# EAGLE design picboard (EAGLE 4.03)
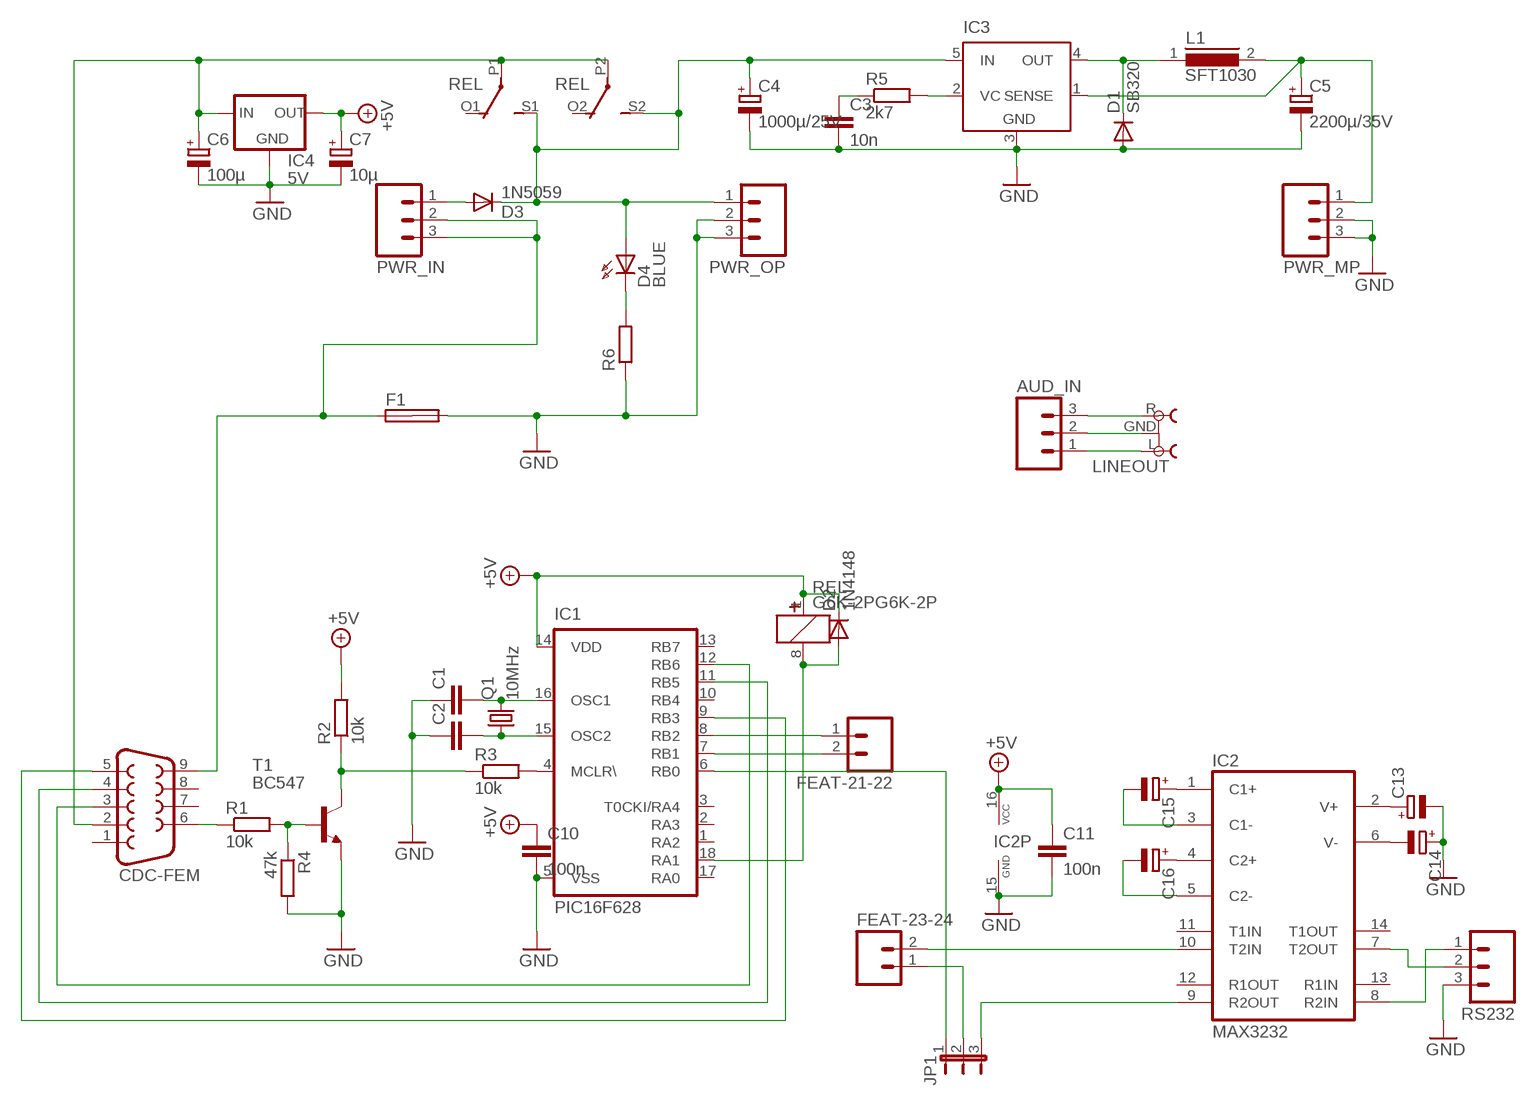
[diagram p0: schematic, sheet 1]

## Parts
AUD_IN  M03  [03P]
C1  C-EU025-024X044  [C025-024X044]
C2  C-EU025-024X044  [C025-024X044]
C3  10n  C-EU025-024X044  [C025-024X044]
C4  1000µ/25V  CPOL-EUE5-13  [E5-13]
C5  2200µ/35V  CPOL-EUE7.5-16  [E7,5-16]
C6  100µ  CPOL-EUE2.5-6  [E2,5-6]
C7  10µ  CPOL-EUE2.5-5  [E2,5-5]
C10  100n  C-EU025-024X044  [C025-024X044]
C11  100n  C-EU025-024X044  [C025-024X044]
C13  CPOL-EUE2.5-5  [E2,5-5]
C14  CPOL-EUE2.5-5  [E2,5-5]
C15  CPOL-EUE2.5-5  [E2,5-5]
C16  CPOL-EUE2.5-5  [E2,5-5]
CDC-FEM  F09H  [F09H]
D1  SB320  [DO201-15]
D2  1N4148  [DO35-10]
D3  1N5059  [DO204-10]
D4  BLUE  LED3MM  [LED3MM]
F1  SHK20L  [SHK20L]
FEAT-21-22  M02  [02P]
FEAT-23-24  M02  [02P]
IC1  PIC16F628  PIC16F84AP  [DIL18]
IC2  MAX3232  [DIL16]
IC3  MAX787  [TO220-5]
IC4  5V  78LXX  [78LXX]
JP1  JP2E  [JP2]
L1  SFT1030  [SFT1030]
LINEOUT  CINCH_REICHELTCINCH_2X  [CINCH_2X]
PWR_IN  M03  [03P]
PWR_MP  M03  [03P]
PWR_OP  M03  [03P]
Q1  10MHz  HC49U70  [HC49U70]
R1  10k  R-EU_0207/10  [0207/10]
R2  10k  R-EU_0207/2V  [0207/2V]
R3  10k  R-EU_0207/10  [0207/10]
R4  47k  R-EU_0207/2V  [0207/2V]
R5  2k7  R-EU_0207/10  [0207/10]
R6  R-EU_0207/10  [0207/10]
REL  G6K-2PG6K-2P  [G6K-2P]
RS232  M03  [03P]
T1  BC547  [TO92]

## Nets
+5V: C7.+ C10.2 C11.2 D2.C IC1.14(VDD) IC2.16(VCC) IC4.OUT R2.2 REL.1
+5V-SW: C5.+ IC3.1(SENSE) L1.2 PWR_MP.1
GND: C1.2 C2.2 C3.1 C4.- C5.- C6.- C7.- C10.1 C11.1 C13.- C14.+ D1.A F1.2A IC1.5(VSS) IC2.15(GND) IC3.3(GND) IC4.GND PWR_MP.2 PWR_MP.3 PWR_OP.2 PWR_OP.3 R4.2 R6.1 RS232.3 T1.1(E)
N$1: C6.+ CDC-FEM.2 IC4.IN REL.P1(P) REL.P2(P)
N$2: CDC-FEM.3 IC1.12(RB6)
N$3: CDC-FEM.4 IC1.11(RB5)
N$4: CDC-FEM.5 IC1.9(RB3)
N$5: C1.1 IC1.16(OSC1) Q1.2
N$6: CDC-FEM.6 R1.1
N$7: R1.2 R4.1 T1.2(B)
N$8: R2.1 R3.1 T1.3(C)
N$9: C4.+ D3.C D4.A IC3.5(IN) PWR_OP.1 REL.S1(S) REL.S2(S)
N$10: IC1.4(MCLR\) R3.2
N$11: C2.1 IC1.15(OSC2) Q1.1
N$12: CDC-FEM.9 F1.1A PWR_IN.2 PWR_IN.3
N$13: D1.C IC3.4(OUT) L1.1
N$14: D3.A PWR_IN.1
N$15: D2.A IC1.18(RA1) REL.8
N$16: FEAT-21-22.1 IC1.8(RB2)
N$17: IC1.6(RB0) JP1.1
N$18: IC2.9(R2OUT) JP1.3
N$19: FEAT-23-24.1 JP1.2
N$20: FEAT-23-24.2 IC2.10(T2IN)
N$21: FEAT-21-22.2 IC1.7(RB1)
N$23: IC2.8(R2IN) RS232.1
N$24: IC3.2(VC) R5.2
N$25: IC2.7(T2OUT) RS232.2
N$27: C3.2 R5.1
N$28: AUD_IN.3 LINEOUT.R
N$29: D4.K(C) R6.2
N$34: C15.+ IC2.1(C1+)
N$35: C15.- IC2.3(C1-)
N$36: C16.+ IC2.4(C2+)
N$37: C16.- IC2.5(C2-)
N$41: AUD_IN.1 LINEOUT.L
N$42: C14.- IC2.6(V-)
N$43: C13.+ IC2.2(V+)
N$44: AUD_IN.2 LINEOUT.GND
Unconnected: CDC-FEM.1 CDC-FEM.7 CDC-FEM.8 F1.1B F1.2B IC1.1(RA2) IC1.2(RA3) IC1.3(T0CKI/RA4) IC1.10(RB4) IC1.13(RB7) IC1.17(RA0) IC2.11(T1IN) IC2.12(R1OUT) IC2.13(R1IN) IC2.14(T1OUT) REL.O1(O) REL.O2(O)

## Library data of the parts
AUD_IN PWR_IN PWR_MP PWR_OP RS232 = con-amp-quick:M03: AMP QUICK CONNECTOR
C1-C3 C10 C11 = rcl:C-EU: CAPACITOR, European symbol
C4-C7 C13-C16 = rcl:CPOL-EU: POLARIZED CAPACITOR, European symbol
CDC-FEM = con-subd:F09H: HARTING SUB-D
D1 = diode:SB320: DIODE
D2 = diode:1N4148: DIODE
D3 = diode:1N5059: DIODE
D4 = led:LED3MM: LED
F1 = fuse:SHK20L: FUSE HOLDER 5 x 20 mm, SH contact, SHH1 Schukat, E1073 Buerklin
FEAT-21-22 FEAT-23-24 = con-amp-quick:M02: AMP QUICK CONNECTOR
IC1 = microchip:PIC16F8*: MICROCONTROLLER 8-Bit PIC16F8X Family - CMOS Flash/EEPROM Pin Compatible : PIC16F83, PIC16CR83, PIC16F84A, PIC16CR84 see also PIC16C*
IC2 = maxim:MAX3232: RS232 TRANSEIVER
IC3 = _mylib:MAX787: VOLTAGE REGULATOR with shutdown
IC4 = v-reg:78LXX: VOLTAGE REGULATOR
JP1 = jumper:JP2E: JUMPER
L1 = inductors:SFT1030: INDUCTOR
LINEOUT = _mylib:CINCH_REICHELT
Q1 = crystal:HC49U70: CRYSTAL
R1-R6 = rcl:R-EU_: RESISTOR, European symbol
REL = _mylib:G6K-2P
T1 = transistor-npn:BC547: NPN TRANSISTOR

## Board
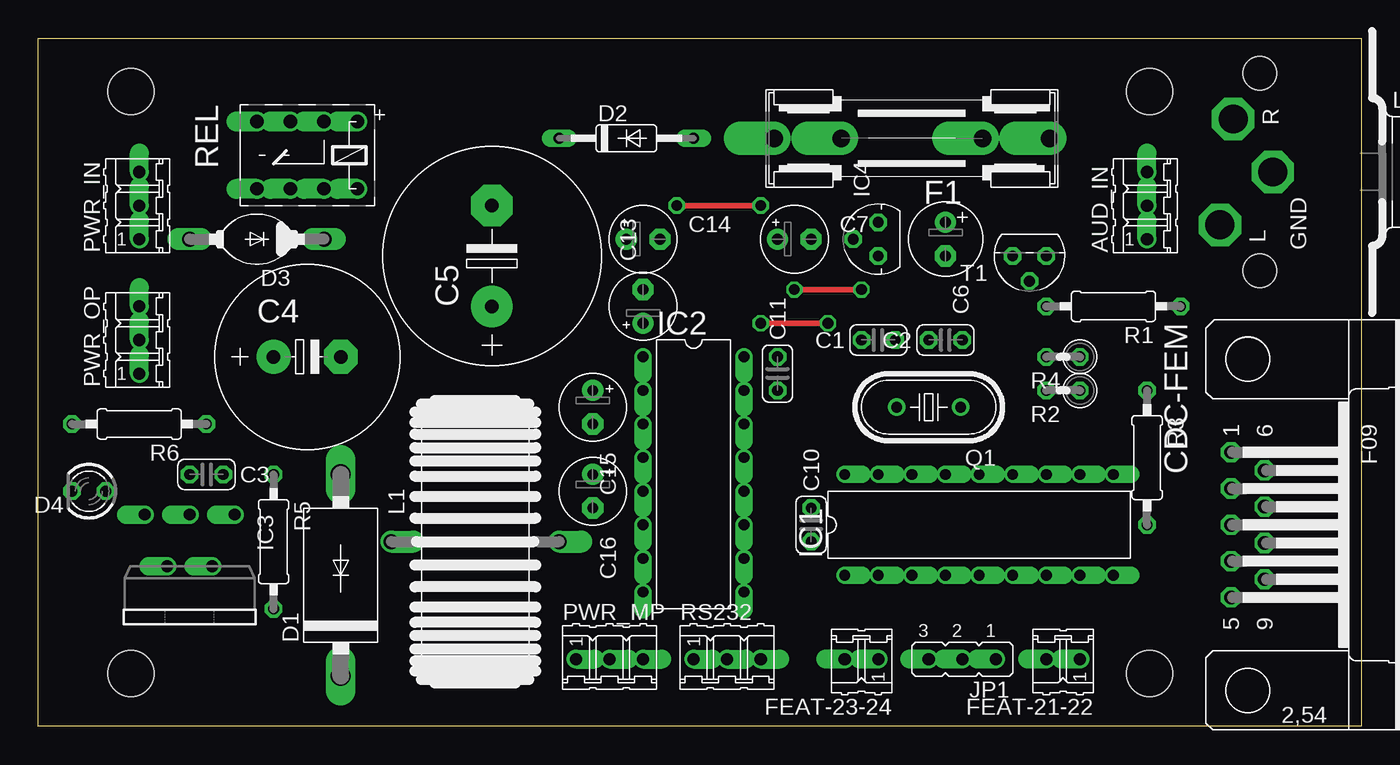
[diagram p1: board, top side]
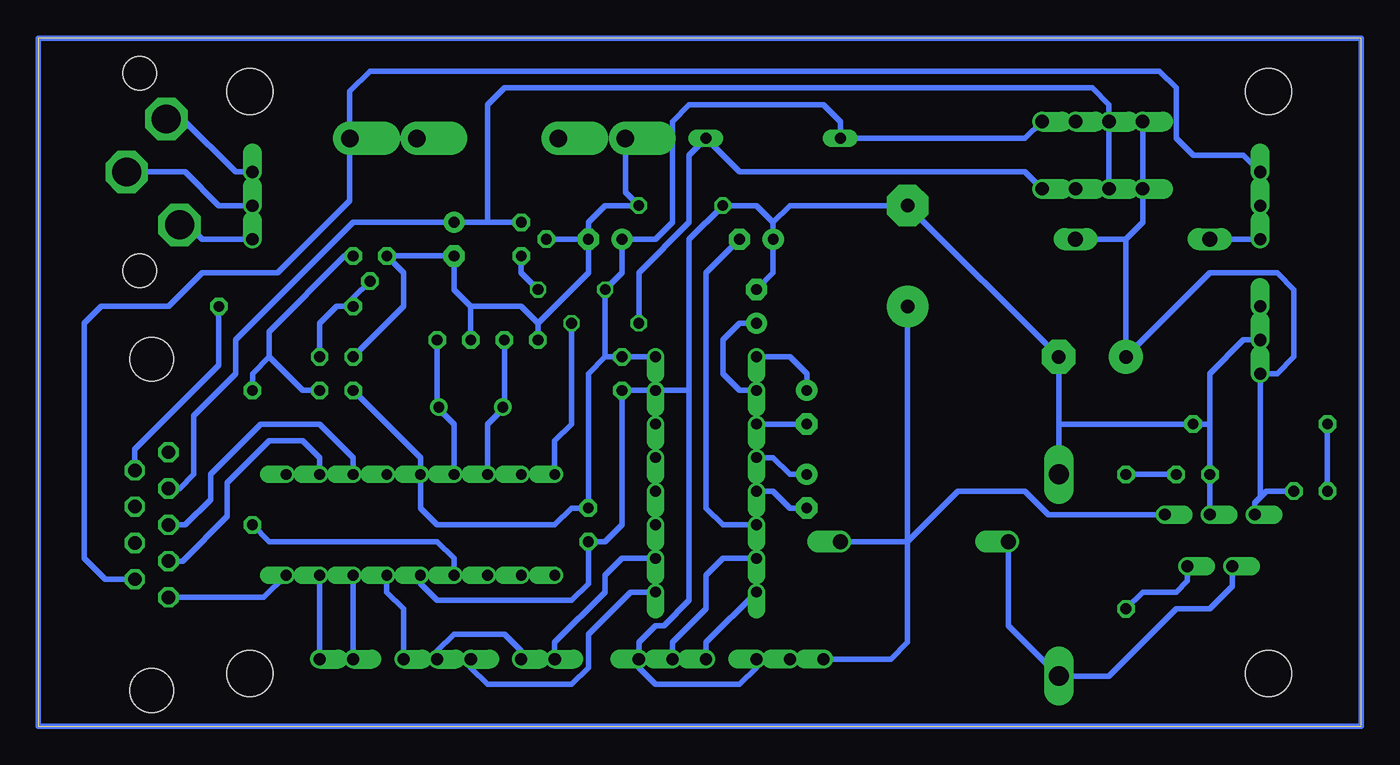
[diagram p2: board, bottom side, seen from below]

Size 100 x 52 mm. Coordinates in mm from the lower left corner, seen from the top.
Outline: 0,0 0,52 100,52 100,0 0,0
Copper layers used: Top, Bottom
Holes 3.5 mm at 7,48 7,4 84,4 84,48

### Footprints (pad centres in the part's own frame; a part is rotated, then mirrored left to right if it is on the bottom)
03P = drill 0.914 offset: 1 -2.54,0; 2 0,0; 3 2.54,0
C025-024X044 = drill 0.813 octagon: 1 -1.27,0; 2 1.27,0
E5-13 = drill 1.016 pad 2.54 round: + -2.54,0 | drill 1.016 pad 2.54 octagon: - 2.54,0
E7,5-16 = drill 1.016 pad 3.15 round: + -3.81,0 | drill 1.016 pad 3.15 octagon: - 3.81,0
E2,5-6 = drill 0.813 pad 1.6 round: + -1.27,0 | drill 0.813 pad 1.6 octagon: - 1.27,0
E2,5-5 = drill 0.813 pad 1.6 round: + -1.27,0 | drill 0.813 pad 1.6 octagon: - 1.27,0
F09H = drill 1.016 octagon: 1 -5.486,-1.27; 2 -2.743,-1.27; 3 0,-1.27; 4 2.743,-1.27; 5 5.486,-1.27; 6 -4.115,1.27; 7 -1.372,1.27; 8 1.372,1.27; 9 4.115,1.27 | hole 3.302: -12.522,0; 12.522,0
DO201-15 = drill 1.499 long: A 7.62,0; C -7.62,0
DO35-10 = drill 0.813 long: A 5.08,0; C -5.08,0
DO204-10 = drill 1.118 long: A 5.08,0; C -5.08,0
LED3MM = drill 0.813 octagon: A -1.27,0; K 1.27,0
SHK20L = drill 1.321 pad 2.54 offset: 1A -10.414,0; 1B -5.334,0; 2A 10.414,0; 2B 5.334,0
02P = drill 0.914 offset: 1 -1.27,0; 2 1.27,0
DIL18 = drill 0.813 offset: 1 -10.16,-3.81; 2 -7.62,-3.81; 3 -5.08,-3.81; 4 -2.54,-3.81; 5 0,-3.81; 6 2.54,-3.81; 7 5.08,-3.81; 8 7.62,-3.81; 9 10.16,-3.81; 10 10.16,3.81; 11 7.62,3.81; 12 5.08,3.81; 13 2.54,3.81; 14 0,3.81; 15 -2.54,3.81; 16 -5.08,3.81; 17 -7.62,3.81; 18 -10.16,3.81
DIL16 = drill 0.813 offset: 1 -8.89,-3.81; 2 -6.35,-3.81; 3 -3.81,-3.81; 4 -1.27,-3.81; 5 1.27,-3.81; 6 3.81,-3.81; 7 6.35,-3.81; 8 8.89,-3.81; 9 8.89,3.81; 10 6.35,3.81; 11 3.81,3.81; 12 1.27,3.81; 13 -1.27,3.81; 14 -3.81,3.81; 15 -6.35,3.81; 16 -8.89,3.81
TO220-5 = drill 0.9 offset: 1 -3.4,-8.4; 2 -1.7,-4.5; 3 0,-8.4; 4 1.7,-4.5; 5 3.4,-8.4
78LXX = drill 0.813 octagon: GND 0,1.905; IN 1.27,0; OUT -1.27,0
JP2 = drill 0.914 offset: 1 -2.54,0; 2 0,0; 3 2.54,0
SFT1030 = drill 1.118 offset: 1 -6.35,0; 2 6.35,0
CINCH_2X = drill 2.184 octagon: GND 0,-7; L 4,-11; R -4,-10 | hole 2.54: -7.46,-8; 7.46,-8
HC49U70 = drill 0.813 round: 1 -2.413,0; 2 2.413,0
0207/10 = drill 0.813 octagon: 1 -5.08,0; 2 5.08,0
0207/2V = drill 0.813 octagon: 1 -1.27,0; 2 1.27,0
G6K-2P = drill 1.016 offset: 1 -3.81,-3.81; 8 -3.81,1.27; O1 -1.27,-3.81; O2 -1.27,1.27; P1 1.27,-3.81; P2 1.27,1.27; S1 3.81,-3.81; S2 3.81,1.27
TO92 = drill 0.813 octagon: 1 1.27,0; 2 0,1.905; 3 -1.27,0

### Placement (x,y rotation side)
AUD_IN  83.82,39.37 90 top
C1  63.5,29.21 180 top
C2  68.58,29.21 180 top
C3  12.7,19.05 0 top
C4  20.32,27.94 0 top
C5  34.29,35.56 90 top
C6  68.58,36.83 270 top
C7  57.15,36.83 0 top
C10  58.42,15.24 90 top
C11  55.88,26.67 90 top
C13  45.72,31.75 90 top
C14  45.72,36.83 0 top
C15  41.91,24.13 270 top
C16  41.91,17.78 270 top
CDC-FEM  91.44,15.24 270 top
D1  22.86,11.43 90 top
D2  44.45,44.45 0 top
D3  16.51,36.83 180 top
D4  3.81,17.78 180 top
F1  66.04,44.45 180 top
FEAT-21-22  77.47,5.08 180 top
FEAT-23-24  62.23,5.08 180 top
IC1  71.12,15.24 0 top
IC2  49.53,19.05 270 top
IC3  11.43,7.62 180 top
IC4  63.5,36.83 90 top
JP1  69.85,5.08 180 top
L1  33.02,13.97 0 top
LINEOUT  100.33,41.91 270 top
PWR_IN  7.62,39.37 90 top
PWR_MP  43.18,5.08 0 top
PWR_OP  7.62,29.21 90 top
Q1  67.31,24.13 180 top
R1  81.28,31.75 180 top
R2  77.47,25.4 180 top
R3  83.82,20.32 270 top
R4  77.47,27.94 180 top
R5  17.78,13.97 270 top
R6  7.62,22.86 180 top
REL  20.32,41.91 180 top
RS232  52.07,5.08 0 top
T1  74.93,35.56 180 top

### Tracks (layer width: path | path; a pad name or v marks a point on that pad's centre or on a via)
+5V  (via drill 0.81)
  Top 0.406: v57.15,33.02 v62.23,33.02
  Bottom 0.406: R2.2 71.12,20.32 IC1.14 71.12,16.51 69.85,15.24 60.96,15.24 59.69,16.51 C10.2 58.42,26.67 57.15,27.94 | v62.23,33.02 63.5,34.29 IC4.OUT | IC2.16 C11.2 57.15,27.94 | 57.15,27.94 v57.15,33.02 55.88,34.29 C7.+ 53.34,36.83 52.07,38.1 52.07,45.72 50.8,46.99 40.64,46.99 39.37,45.72 D2.C 25.4,44.45 REL.1
+5V-SW
  Bottom 0.406: 34.29,13.97 C5.+ | 34.29,13.97 L1.2 | IC3.1 23.64,16.02 25.4,17.78 30.48,17.78 34.29,13.97 | PWR_MP.1 35.56,5.08 34.29,6.35 34.29,13.97
GND  (via drill 0.81)
  Top 0.406: v48.26,39.37 v54.61,39.37
  Bottom 0.406: IC1.5 71.12,10.79 69.85,9.53 59.69,9.53 58.42,10.79 C10.1 57.15,13.97 55.88,15.24 C11.1 IC2.15 50.8,25.4 | C7.- 58.42,38.1 57.15,39.37 v54.61,39.37 55.63,40.39 F1.2A | 62.23,30.48 63.5,31.75 67.31,31.75 | 67.31,31.75 C2.2 | 67.31,31.75 68.58,33.02 C6.- T1.1 72.39,34.29 72.39,31.75 R4.2 | 50.8,25.4 50.8,36.83 v48.26,39.37 45.72,39.37 44.45,38.1 | C7.- 58.42,34.29 62.23,30.48 | 62.23,30.48 C1.2 | 44.45,38.1 C14.+ 44.45,34.29 C13.- | C7.- IC4.GND | 50.8,25.4 50.8,9.53 52.7,7.62 53.34,7.62 54.61,6.35 RS232.3 54.61,4.45 53.34,3.17 46.99,3.17 45.72,4.45 PWR_MP.3 PWR_MP.2 | IC3.3 C3.1 11.43,22.86 | 22.86,22.86 R6.1 11.43,22.86 | 22.86,22.86 D1.A | 22.86,22.86 C4.- C5.- 43.18,39.37 44.45,38.1 | 11.43,22.86 11.43,26.67 8.89,29.21 PWR_OP.2 PWR_OP.3
N$1
  Bottom 0.406: 66.04,38.1 66.04,46.99 64.77,48.26 20.32,48.26 19.05,46.99 REL.P1 REL.P2 | CDC-FEM.2 89.33,17.98 88.27,19.05 88.27,23.5 85.09,26.67 85.09,29.21 76.2,38.1 C6.+ 66.04,38.1 | 66.04,38.1 IC4.IN
N$2
  Bottom 0.406: IC1.12 76.2,20.32 78.74,22.86 83.19,22.86 87,19.05 87,17.14 88.9,15.24 CDC-FEM.3
N$3
  Bottom 0.406: IC1.11 78.74,20.32 80.01,21.59 82.55,21.59 85.72,18.41 85.72,15.88 89.1,12.5 CDC-FEM.4
N$4
  Bottom 0.406: CDC-FEM.5 82.96,9.75 IC1.9
N$5
  Bottom 0.406: IC1.16 66.04,22.86 64.77,24.13 | 64.77,24.13 Q1.2 | 64.77,24.13 C1.1
N$6
  Bottom 0.406: CDC-FEM.6 92.71,20.95 86.36,27.3 R1.1
N$7
  Bottom 0.406: R4.1 78.74,30.48 77.47,31.75 R1.2 76.2,32.38 T1.2
N$8
  Bottom 0.406: R2.1 80.01,25.4 82.55,27.94 | 82.55,27.94 82.55,29.84 76.83,35.56 T1.3 | 82.55,27.94 83.82,26.67 R3.1
N$9
  Bottom 0.406: 17.78,36.83 C4.+ 11.43,34.29 6.35,34.29 5.08,33.02 5.08,27.94 6.35,26.67 PWR_OP.1 7.62,17.33 7.17,17.78 | 17.78,36.83 16.51,38.1 REL.S2 REL.S1 | 17.78,36.83 D3.C | IC3.5 8.03,16.92 7.17,17.78 | D4.A 7.17,17.78
N$10
  Bottom 0.406: IC1.4 68.58,12.7 69.85,13.97 82.55,13.97 R3.2
N$11
  Bottom 0.406: 69.85,24.13 Q1.1 | IC1.15 68.58,22.86 69.85,24.13 | 69.85,24.13 C2.1
N$12
  Bottom 0.406: CDC-FEM.9 94.94,11.12 96.52,12.7 96.52,30.48 95.25,31.75 90.17,31.75 87.63,34.29 81.92,34.29 76.45,39.75 F1.1A 76.45,48.01 74.93,49.53 15.24,49.53 13.97,48.26 13.97,44.45 12.7,43.18 8.89,43.18 PWR_IN.3 | PWR_IN.3 PWR_IN.2 PWR_IN.3
N$13
  Bottom 0.406: IC3.4 9.73,10.59 11.43,8.89 13.97,8.89 19.05,3.81 D1.C 26.67,7.62 L1.1
N$14
  Bottom 0.406: PWR_IN.1 D3.A
N$15  (via drill 0.81)
  Top 0.406: v54.61,30.48 v59.69,30.48
  Bottom 0.406: v54.61,30.48 54.61,34.29 50.8,38.1 50.8,43.18 D2.A 46.99,41.91 25.4,41.91 REL.8 | IC1.18 60.96,21.59 59.69,22.86 v59.69,30.48
N$16
  Bottom 0.406: FEAT-21-22.1 IC1.8
N$17
  Bottom 0.406: JP1.1 72.39,8.89 73.66,10.16 IC1.6
N$18
  Bottom 0.406: IC2.9 55.24,10.16 58.42,6.99 58.42,4.45 59.69,3.17 66.04,3.17 67.31,4.45 JP1.3
N$19
  Bottom 0.406: FEAT-23-24.1 63.5,5.71 64.77,6.99 68.58,6.99 69.85,5.71 JP1.2
N$20
  Bottom 0.406: IC2.10 55.88,12.7 57.15,11.43 57.15,10.16 60.96,6.35 FEAT-23-24.2
N$21
  Bottom 0.406: FEAT-21-22.2 IC1.7
N$22
  Bottom 0.406: 0,0 100,0 100,52 0,52 0,0
N$23
  Bottom 0.406: RS232.1 49.53,6.35 IC2.8
N$24
  Bottom 0.406: IC3.2 13.13,11 13.97,10.16 16.51,10.16 R5.2
N$25
  Bottom 0.406: RS232.2 52.07,6.35 49.53,8.89 49.53,11.43 48.26,12.7 IC2.7
N$27
  Bottom 0.406: C3.2 R5.1
N$28
  Bottom 0.406: LINEOUT.R 89.09,45.91 85.09,41.91 AUD_IN.3
N$29
  Bottom 0.406: D4.K R6.2
N$34
  Bottom 0.406: C15.+ 41.91,26.67 43.18,27.94 IC2.1
N$35
  Bottom 0.406: C15.- IC2.3
N$36
  Bottom 0.406: C16.+ 43.18,19.05 44.45,20.32 IC2.4
N$37
  Bottom 0.406: C16.- 43.18,16.51 44.45,17.78 IC2.5
N$41
  Bottom 0.406: LINEOUT.L 88.71,37.91 87.63,36.83 AUD_IN.1
N$42
  Bottom 0.406: C14.- 49.53,34.29 49.53,16.51 48.26,15.24 IC2.6
N$43
  Bottom 0.406: C13.+ 46.99,30.48 48.26,29.21 48.26,26.67 46.99,25.4 IC2.2
N$44
  Bottom 0.406: LINEOUT.GND 88.9,41.91 86.36,39.37 AUD_IN.2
